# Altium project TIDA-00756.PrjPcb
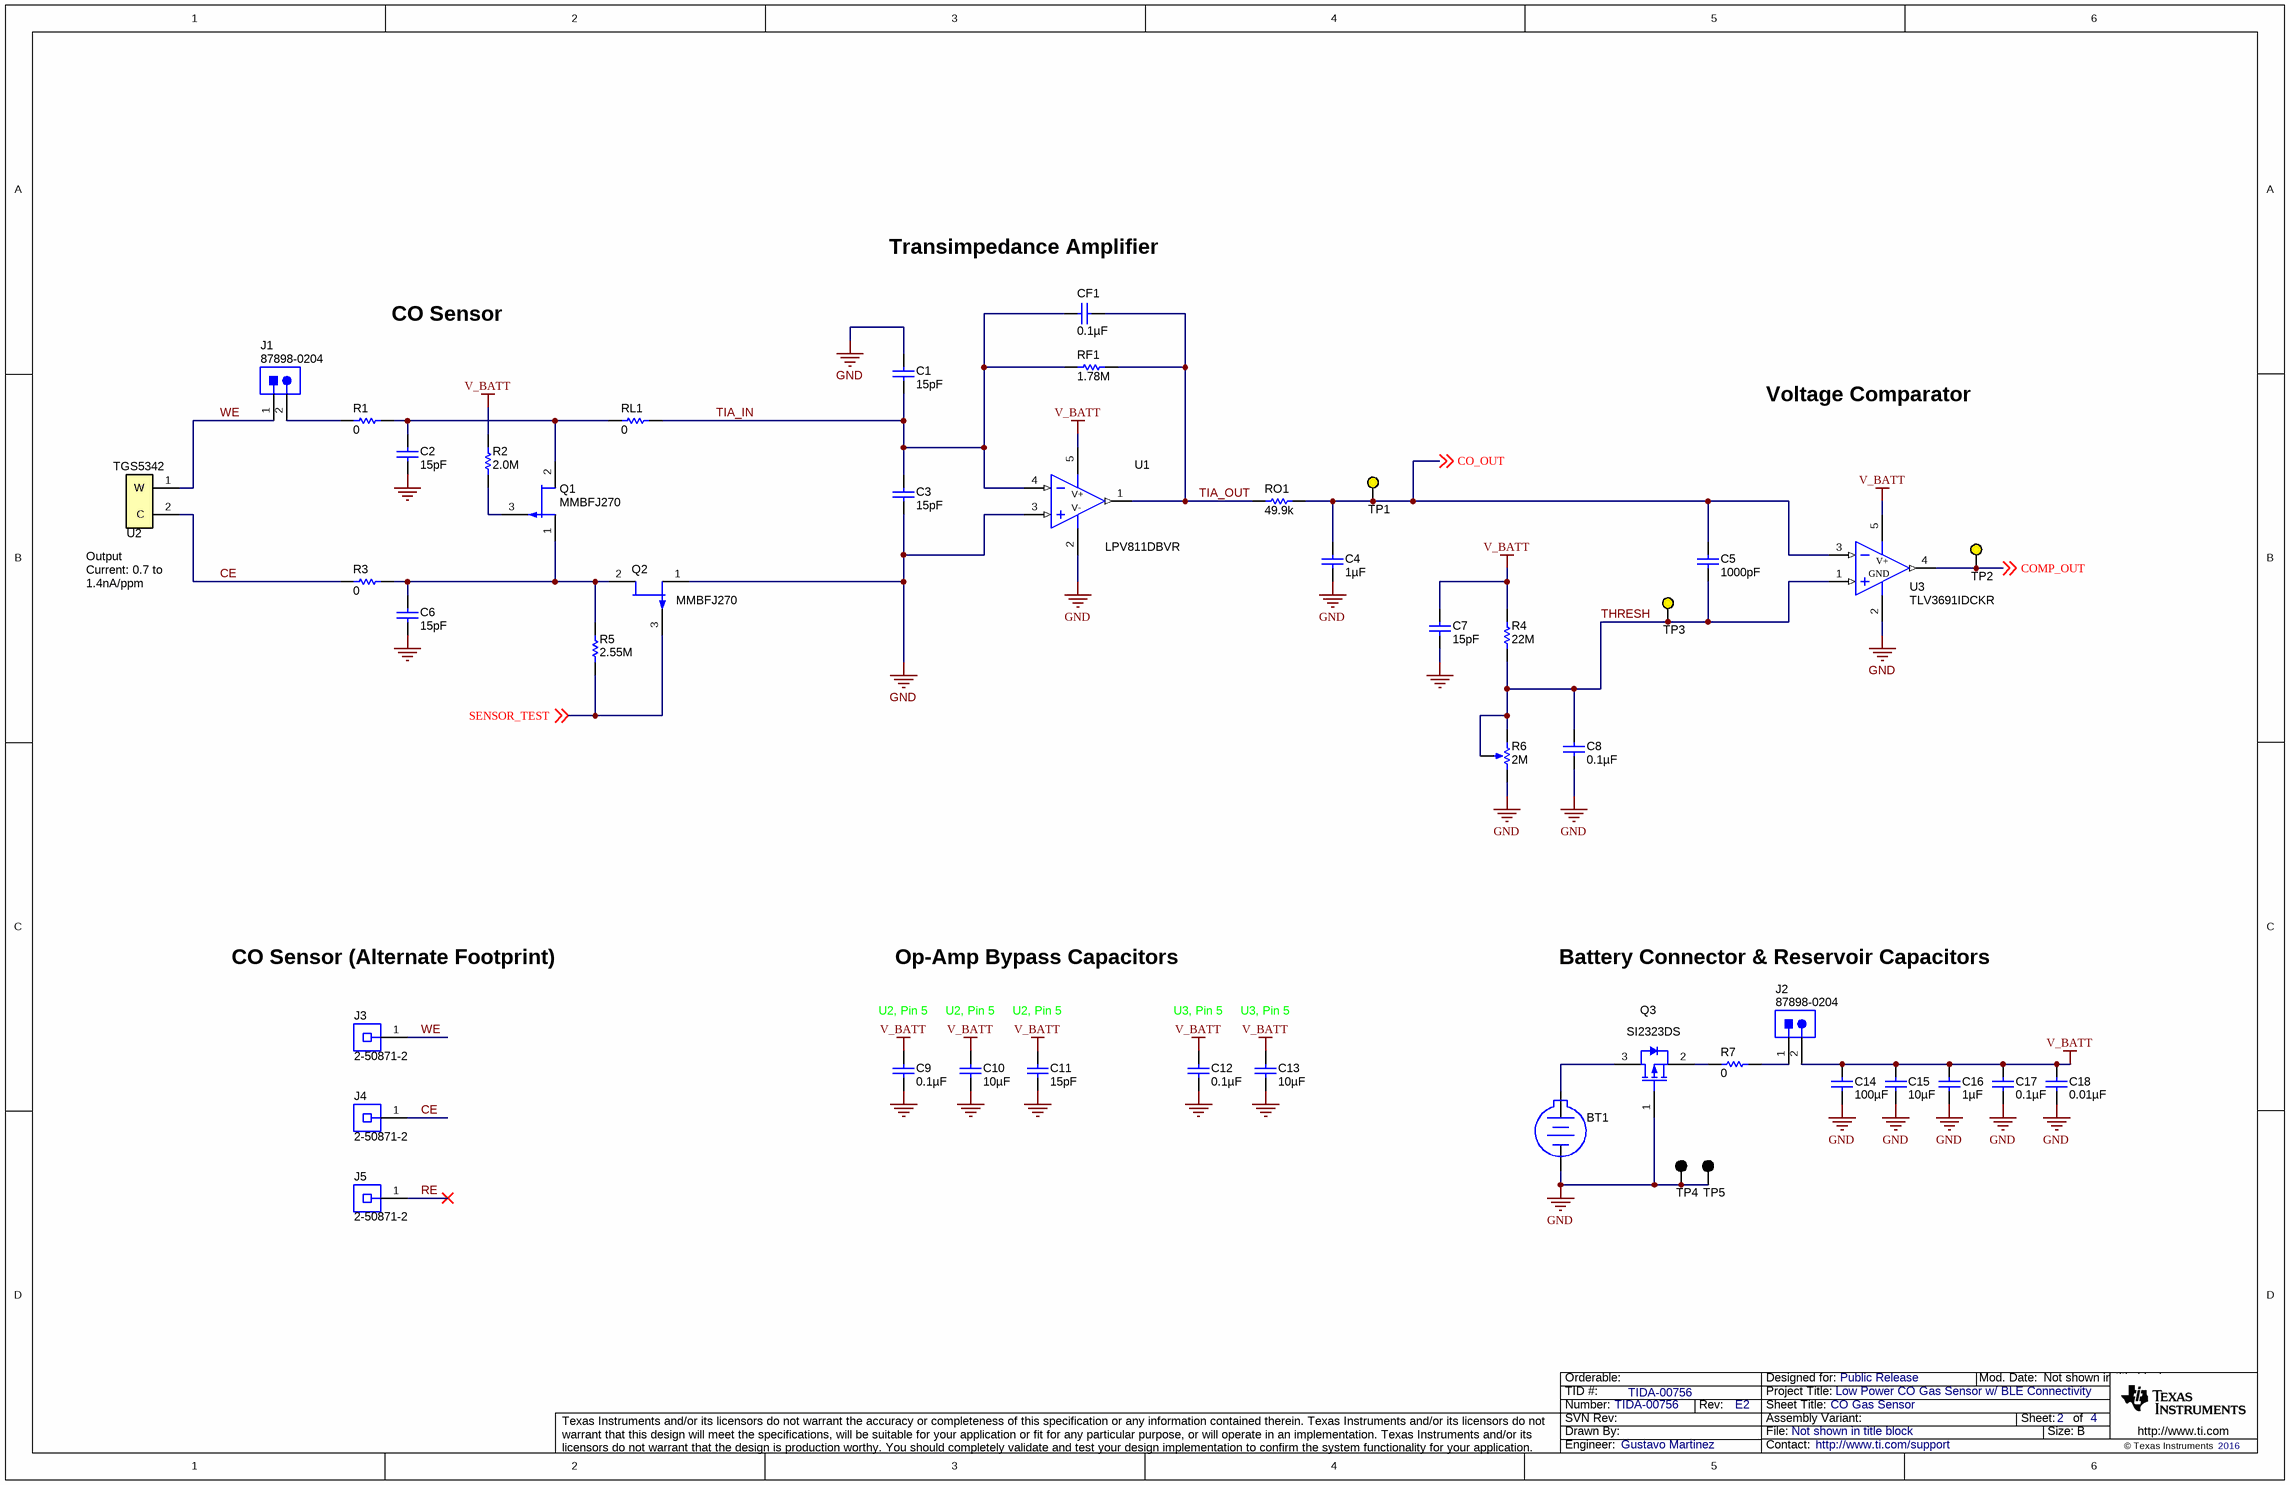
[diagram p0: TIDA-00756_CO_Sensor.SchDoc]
CopyrightYear: 2016; PCB_Layout: Krypton Solutions/RS; PCB_Rev: E2; PRJ_Customer: Public Release; PRJ_Engineer: Gustavo Martinez; PRJ_Number: TIDA-00756; PRJ_Title: Low Power CO Gas Sensor w/ BLE Connectivity; SCH_Rev: E2; TechSupport: http://www.ti.com/support; TID: TIDA-00756
4 sheets, 131 parts. Net scope: global (net labels, ports and power ports of the same name join across sheets).
Board file: TIDA-00756.PcbDoc
Sheets:
  TIDA-00756_CO_Sensor.SchDoc
  TIDA-00756_CoverSheet.SchDoc
  TIDA-00756_Hardware.SchDoc
  TIDA-00756_MCU.SchDoc

## Sheet TIDA-00756_CO_Sensor.SchDoc: CO Gas Sensor
size 431 x 279 mm; Date: Not shown in title block; ApprovedBy: Not shown in title block; CheckedBy: Not shown in title block; Author: Not shown in title block; CompanyName: Not shown in title block; Engineer: Not shown in title block; Organization: Not shown in title block; Address1: Not shown in title block; Address2: Not shown in title block; Address3: Not shown in title block; Address4: Not shown in title block; DocumentNumber: 2; Revision: Use project parameter SCH_Rev; SheetNumber: 2; SheetTotal: 4; PageSetup: Record=PageOptions¦CenterHorizontal=True¦CenterVertical=True¦PrintScale=0.62¦XCorrection=1.00¦YCorrection=1.00¦PrintKind=0¦BorderSize=5000000¦LeftOffset=0¦BottomOffset=0¦Orientation=2¦PaperLength=1000¦PaperWidth=1000¦Scale=100¦PaperSource=15¦PrintQuality=600¦MediaType=1¦DitherType=10¦PrintScaleMode=1¦PaperKind=Letter

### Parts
BT1  BS-7  [BAT_BS-7]  (value not drawn)
C1  ValueDisplayed: 15pF  [0402]  (hidden comment: CC0402JRNPO9BN150)
C2  ValueDisplayed: 15pF  [0402]  (hidden comment: CC0402JRNPO9BN150)
C3  ValueDisplayed: 15pF  [0402]  (hidden comment: CC0402JRNPO9BN150)
C4  ValueDisplayed: 1µF  [0603]  (hidden comment: C1608X5R1E105K080AC)
C5  ValueDisplayed: 1000pF  [0402]  (hidden comment: C0402C102J3RACTU)
C6  ValueDisplayed: 15pF  [0402]  (hidden comment: CC0402JRNPO9BN150)
C7  ValueDisplayed: 15pF  [0402]  (hidden comment: CC0402JRNPO9BN150)
C8  ValueDisplayed: 0.1µF  [0402]  (hidden comment: C1005X7R1H104K)
C9  ValueDisplayed: 0.1µF  [0603L]  (hidden comment: C0603C104K8RACTU)
C10  ValueDisplayed: 10µF  [0805_HV]  (hidden comment: C2012X5R0J106M)
C11  ValueDisplayed: 15pF  [0402]  (hidden comment: CC0402JRNPO9BN150)
C12  ValueDisplayed: 0.1µF  [0603L]  (hidden comment: C0603C104K8RACTU)
C13  ValueDisplayed: 10µF  [0805_HV]  (hidden comment: C2012X5R0J106M)
C14  ValueDisplayed: 100µF  [1206_190]  (hidden comment: C3216X5R1A107M160AC)
C15  ValueDisplayed: 10µF  [0603]  (hidden comment: C1608X5R0J106M)
C16  ValueDisplayed: 1µF  [0603]  (hidden comment: C1608X7R1C105K)
C17  ValueDisplayed: 0.1µF  [0402]  (hidden comment: C1005X7R1H104K050BB)
C18  ValueDisplayed: 0.01µF  [0402]  (hidden comment: C1005X7R1C103K050BA)
CF1  ValueDisplayed: 0.1µF  [0805_HV]  (hidden comment: 08053C104KAT2A)
J1  87898-0204  [Molex_87898-0204]
J2  87898-0204  [Molex_87898-0204]
J3  2-50871-2  [TE_2-50871-2]
J4  2-50871-2  [TE_2-50871-2]
J5  2-50871-2  [TE_2-50871-2]
Q1  MMBFJ270  [SOT-23]
Q2  MMBFJ270  [SOT-23]
Q3  SI2323DS  [SOT-23]
R1  ValueDisplayed: 0  [0603]  (hidden comment: CRCW06030000Z0EA)
R2  ValueDisplayed: 2.0M  [0805_HV]  (hidden comment: CRCW08052M00JNEA)
R3  ValueDisplayed: 0  [0603]  (hidden comment: CRCW06030000Z0EA)
R4  ValueDisplayed: 22M  [0805_HV]  (hidden comment: ERJ-6GEYK226V)
R5  ValueDisplayed: 2.55M  [0805_HV]  (hidden comment: CRCW08052M55FKEA)
R6  value 2M  [TRIM_3224W]  (hidden comment: 3224W-1-205E)
R7  ValueDisplayed: 0  [0805_HV]  (hidden comment: CRCW08050000Z0EA)
RF1  ValueDisplayed: 1.78M  [0805_HV]  (hidden comment: CRCW08051M78FKEA)
RL1  ValueDisplayed: 0  [0805_HV]  (hidden comment: CRCW08050000Z0EA)
RO1  ValueDisplayed: 49.9k  [0603]  (hidden comment: CRCW060349K9FKEA)
TP1  5004  [Keystone5004]  (value not drawn)
TP2  5004  [Keystone5004]  (value not drawn)
TP3  5004  [Keystone5004]  (value not drawn)
TP4  5011  [Keystone5011]  (value not drawn)
TP5  5011  [Keystone5011]  (value not drawn)
U1  LPV811DBVR  [DBV0005A_N]
U2  TGS5342  [FIGARO_TGS5342]
U3  TLV3691IDCKR  [DCK0005A_N]

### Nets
GND: BT1.2(-) C1.1 C2.2 C3.2 C4.2 C6.2 C7.2 C8.2 C9.1 C10.1 C11.2 C12.1 C13.1 C14.2 C15.2 C16.2 C17.2 C18.2 Q2.1(D) Q3.1(G) R6.3(CW) TP4.1 TP5.1 U1.2(V-) U1.3(IN+) U3.2(GND)
V_BATT: C7.1 C9.2 C10.2 C11.1 C12.2 C13.2 C14.1 C15.1 C16.1 C17.1 C18.1 J2.2 R2.1 R4.2 U1.5(V+) U3.5(V+)
CE: J4.1 R3.1 U2.2(C)
CO_OUT: C4.1 C5.1 RO1.2 TP1.1 U3.3(IN-) ; off-sheet CO_OUT
COMP_OUT: TP2.1 U3.4(OUT) ; off-sheet COMP_OUT
RE: J5.1
SENSOR_TEST: Q2.3(G) R5.2 ; off-sheet SENSOR_TEST
THRESH: C5.2 C8.1 R4.1 R6.1(CCW) R6.2(WIPER) TP3.1 U3.1(IN+)
TIA_IN: C1.2 C3.1 CF1.2 RF1.1 RL1.2 U1.4(IN-)
TIA_OUT: CF1.1 RF1.2 RO1.1 U1.1(OUT)
WE: J1.1 J3.1 U2.1(W)
NetBT1_1: BT1.1(+) Q3.3(D)
NetC2_1: C2.1 Q1.2(S) R1.2 RL1.1
NetC6_1: C6.1 Q1.1(D) Q2.2(S) R3.2 R5.1
NetJ1_2: J1.2 R1.1
NetJ2_1: J2.1 R7.2
NetQ1_3: Q1.3(G) R2.2
NetQ3_2: Q3.2(S) R7.1

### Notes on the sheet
- Transimpedance Amplifier
- CO Sensor
- Voltage Comparator
- (near U2) Output Current: 0.7 to 1.4nA/ppm
- CO Sensor (Alternate Footprint)
- Op-Amp Bypass Capacitors
- Battery Connector & Reservoir Capacitors
- U2, Pin 5
- U3, Pin 5

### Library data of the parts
BT1 = BS-7: Battery Holder, CR2032, Retainer clip, TH; Manufacturer: Memory Protection Devices; SymbolCreator: a0412235
C1-C3 C6 C7 C11 = CC0402JRNPO9BN150: CAP, CERM, 15 pF, 50 V, +/- 5%, C0G/NP0, 0402; Manufacturer: Yageo America; Polarized: N; CompType: Capacitor; Value: 15pF; U/M: EA; Cap_F: 0.000000000015; Tolerance_%: 5; Value1: Unknown; VDC_V: 50; Value2: 50V; TaMin_C: -55; TaMax_C: 125; AEC Category: Q200
C4 = C1608X5R1E105K080AC: CAP, CERM, 1 µF, 25 V, +/- 10%, X5R, 0603; Manufacturer: TDK; Polarized: N; CompType: Capacitor; Value: 1uF; U/M: EA; Cap_F: 0.000001; Tolerance_%: 10; Value1: Unknown; VDC_V: 25; Value2: 25V; TaMin_C: -55; TaMax_C: 85; AEC Category: Q200
C5 = C0402C102J3RACTU: CAP, CERM, 1000 pF, 25 V, +/- 5%, X7R, 0402; Manufacturer: Kemet; Polarized: N; CompType: Capacitor; Value: 1000pF; U/M: EA; Cap_F: 0.000000001; Tolerance_%: 5; Value1: Unknown; VDC_V: 25; Value2: 25V; TaMin_C: -55; TaMax_C: 125; AEC Category: Q200
C8 = C1005X7R1H104K: CAP, CERM, 0.1 µF, 50 V, +/- 10%, X7R, 0402; Manufacturer: TDK; Polarized: N; CompType: Capacitor; Value: 0.1uF; U/M: EA; Cap_F: 0.0000001; Tolerance_%: 10; Value1: Unknown; VDC_V: 50; Value2: 50V; TaMin_C: -55; TaMax_C: 125; AEC Category: Q200
C9 C12 = C0603C104K8RACTU: CAP, CERM, 0.1 µF, 10 V, +/- 10%, X7R, 0603; Manufacturer: Kemet; Polarized: N; CompType: Capacitor; Value: 0.1uF; U/M: EA; Cap_F: 0.0000001; Tolerance_%: 10; Value1: Unknown; Value2: 10V; TaMin_C: -55; TaMax_C: 125; Cap_Case: 0603
C10 C13 = C2012X5R0J106M: CAP, CERM, 10 µF, 6.3 V, +/- 20%, X5R, 0805; Manufacturer: TDK; Polarized: N; CompType: Capacitor; Value: 10uF; U/M: EA; Cap_F: 0.00001; Tolerance_%: 20; ESR_ohm: 0.0026; Value1: 0.0026 ohm; VDC_V: 6.3; Value2: 6.3V; TaMin_C: -55; TaMax_C: 85; Cap_Case: 0805
C14 = C3216X5R1A107M160AC: CAP, CERM, 100 µF, 10 V, +/- 20%, X5R, 1206_190; Manufacturer: TDK; Polarized: N; CompType: Capacitor; Value: 100uF; U/M: EA; Cap_F: 0.0001; Tolerance_%: 20; Value1: Unknown; VDC_V: 10; Value2: 10V; TaMin_C: -55; TaMax_C: 85; Cap_Case: 1206; AEC Category: Q200
C15 = C1608X5R0J106M: CAP, CERM, 10 µF, 6.3 V, +/- 20%, X5R, 0603; Manufacturer: TDK; Polarized: N; CompType: Capacitor; Value: 10uF; U/M: EA; Cap_F: 0.00001; Tolerance_%: 20; ESR_ohm: 0.005; Value1: 0.005 ohm; VDC_V: 6.3; Value2: 6.3V; IRMS_A: 1.9; TaMin_C: -25; TaMax_C: 85; AEC Category: Q200
C16 = C1608X7R1C105K: CAP, CERM, 1 µF, 16 V, +/- 10%, X7R, 0603; Manufacturer: TDK; Polarized: N; CompType: Capacitor; Value: 1uF; U/M: EA; Cap_F: 0.000001; Tolerance_%: 10; ESR_ohm: 0.0057; Value1: 0.0057 ohm; VDC_V: 16; Value2: 16V; TaMin_C: -55; TaMax_C: 125; AEC Category: Q200
C17 = C1005X7R1H104K050BB: CAP, CERM, 0.1 µF, 50 V, +/- 10%, X7R, 0402; Manufacturer: TDK; Polarized: N; CompType: Capacitor; Value: 0.1uF; U/M: EA; Cap_F: 0.0000001; Tolerance_%: 10; Value1: Unknown; VDC_V: 50; Value2: 50V; TaMin_C: -55; TaMax_C: 125; AEC Category: Q200
C18 = C1005X7R1C103K050BA: CAP, CERM, 0.01 µF, 16 V, +/- 10%, X7R, 0402; Manufacturer: TDK; Polarized: N; CompType: Capacitor; Value: 0.01uF; U/M: EA; Cap_F: 0.00000001; Tolerance_%: 10; ESR_ohm: 0.0623; Value1: 0.0623 ohm; VDC_V: 16; Value2: 16V; TaMin_C: -55; TaMax_C: 125; AEC Category: Q200
CF1 = 08053C104KAT2A: CAP, CERM, 0.1 µF, 25 V, +/- 10%, X7R, 0805; Manufacturer: AVX; Polarized: N; CompType: Capacitor; Value: 0.1uF; U/M: EA; Cap_F: 0.0000001; Tolerance_%: 10; ESR_ohm: 0.28; Value1: 0.28 ohm; VDC_V: 25; Value2: 25V; TaMin_C: -55; TaMax_C: 125; Cap_Case: 0805; AEC Category: Q200
J1 J2 = 87898-0204: Header, 2.54 mm, 2x1, Gold, R/A, SMT; Manufacturer: Molex; SymbolCreator: a0412235; U/M: EA
J3-J5 = 2-50871-2: CONN SOCKET RCPT .056-.065 30AU, Gold, TH; Manufacturer: TE Connectivity; SymbolCreator: a0799628; CompType: Pin Receptacle
Q1 Q2 = MMBFJ270: JFET, P-CH, -30 V, -0.015 A, SOT-23; Manufacturer: Fairchild Semiconductor; Alternate Manufacturer: None; SymbolCreator: Altium; CompType: MOSFET; U/M: EA; ChType: P; Value: -30V; Value1: ? ohm; Value2: ? nC; Vgs_V: 30; AEC Category: Q101; AEC Qualified: N
Q3 = SI2323DS: MOSFET, P-CH, -20 V, -3.7 A, SOT-23; Manufacturer: Vishay-Siliconix; Alternate Manufacturer: None; U/M: EA; ChType: P; Value: -20V; Value1: 0.031 ohm; Rdson45_ohm: 0.031; Value2: 12.5 nC; QgTyp_nC: 12.5; Vgs_V: -8; AEC Category: Q101
R1 R3 = CRCW06030000Z0EA: RES, 0, 5%, 0.1 W, 0603; Manufacturer: Vishay-Dale; CompType: Resistor; Value: 0; Value_Code: 0000; Tolerance_%: 5; Power_W: 0.1; Value2: 0.1W; VDC_V: 75; TempCo: 200 ppm/C; EIA_Code: E24; U/M: EA; AEC Category: Q200
R2 = CRCW08052M00JNEA: RES, 2.0 M, 5%, 0.125 W, 0805; Manufacturer: Vishay-Dale; CompType: Resistor; Value: 2.0Meg; Res_ohm: 2000000; Value_Code: 2M00; Tolerance_%: 5; Power_W: 0.125; Value2: 0.125W; VDC_V: 150; TempCo: 200 ppm/C; EIA_Code: E24; U/M: EA; AEC Category: Q200
R4 = ERJ-6GEYK226V: RES, 22 M, 10%, 0.125 W, 0805; Manufacturer: Panasonic; CompType: Resistor; Value: 22Meg; Res_ohm: 22000000; Value_Code: 22M0; Tolerance_%: 10; Power_W: 0.125; Value2: 0.125W; VDC_V: 150; TempCo: 150 ppm/C; U/M: EA; AEC Category: Q200
R5 = CRCW08052M55FKEA: RES, 2.55 M, 1%, 0.125 W, 0805; Manufacturer: Vishay-Dale; CompType: Resistor; Value: 2.55Meg; Res_ohm: 2550000; Value_Code: 2M55; Tolerance_%: 1; Power_W: 0.125; Value2: 0.125W; VDC_V: 150; TempCo: 100 ppm/C; EIA_Code: E96; U/M: EA; AEC Category: Q200
R6 = 3224W-1-205E: TRIMMER 2M OHM 0.25W SMD; Manufacturer: Bourns; Sim Note: Enter the Resistance value and the set point into parameter fields.; SymbolCreator: a0412235
R7 RL1 = CRCW08050000Z0EA: RES, 0, 5%, 0.125 W, 0805; Manufacturer: Vishay-Dale; CompType: Resistor; Value: 0; Value_Code: 0000; Tolerance_%: 5; Power_W: 0.125; Value2: 0.125W; VDC_V: 150; TempCo: 200 ppm/C; EIA_Code: E24; U/M: EA; AEC Category: Q200
RF1 = CRCW08051M78FKEA: RES, 1.78 M, 1%, 0.125 W, 0805; Manufacturer: Vishay-Dale; CompType: Resistor; Value: 1.78Meg; Res_ohm: 1780000; Value_Code: 1M78; Tolerance_%: 1; Power_W: 0.125; Value2: 0.125W; VDC_V: 150; TempCo: 100 ppm/C; EIA_Code: E96; U/M: EA; AEC Category: Q200
RO1 = CRCW060349K9FKEA: RES, 49.9 k, 1%, 0.1 W, 0603; Manufacturer: Vishay-Dale; CompType: Resistor; Value: 49.9k; Res_ohm: 49900; Value_Code: 49k9; Tolerance_%: 1; Power_W: 0.1; Value2: 0.1W; VDC_V: 75; TempCo: 100 ppm/C; EIA_Code: E96; U/M: EA; AEC Category: Q200
TP1-TP3 = 5004: Test Point, Miniature, Yellow, TH; Manufacturer: Keystone; CompType: Test Point Loop; U/M: EA
TP4 TP5 = 5011: Test Point, Multipurpose, Black, TH; Manufacturer: Keystone; CompType: Test Point Loop; ContactFinish: Silver
U1 = LPV811DBVR: Precision 425 nA Nanopower Operational Amplifier, DBV0005A (SOT-5); Alternate PartNumber: LPV811DBVT; Manufacturer: Texas Instruments; SizeArea_mm2: 8.12; SizeAreaWB_mm2: 14.82; SizeX_mm: 2.8; SizeY_mm: 2.9; SizeZ_mm: 1.45; CompType: IC; U/M: EA
U2 = TGS5342: Carbon Monoxide Detector, TH; Manufacturer: Any; SymbolCreator: Altium
U3 = TLV3691IDCKR: 0.9-V to 6.5-V, Nanopower Comparator, DCK0005A; Alternate PartNumber: TLV3691IDCKT; Manufacturer: Texas Instruments; SymbolCreator: OpAmp IC; CompType: IC; U/M: EA

## Sheet TIDA-00756_CoverSheet.SchDoc: Cover Sheet
size 431 x 279 mm; Date: Not shown in title block; ApprovedBy: Not shown in title block; CheckedBy: Not shown in title block; Author: Not shown in title block; CompanyName: Not shown in title block; Engineer: Not shown in title block; Organization: Not shown in title block; Address1: Not shown in title block; Address2: Not shown in title block; Address3: Not shown in title block; Address4: Not shown in title block; DocumentNumber: 1; Revision: Use project parameter SCH_Rev; SheetNumber: 1; SheetTotal: 4; PageSetup: Record=PageOptions¦CenterHorizontal=True¦CenterVertical=True¦PrintScale=1.00¦XCorrection=1.00¦YCorrection=1.00¦PrintKind=0¦BorderSize=5000000¦LeftOffset=0¦BottomOffset=0¦Orientation=2¦PaperLength=1000¦PaperWidth=1000¦Scale=100¦PaperSource=15¦PrintQuality=600¦MediaType=1¦DitherType=10¦PaperKind=Letter¦PrintScaleMode=1
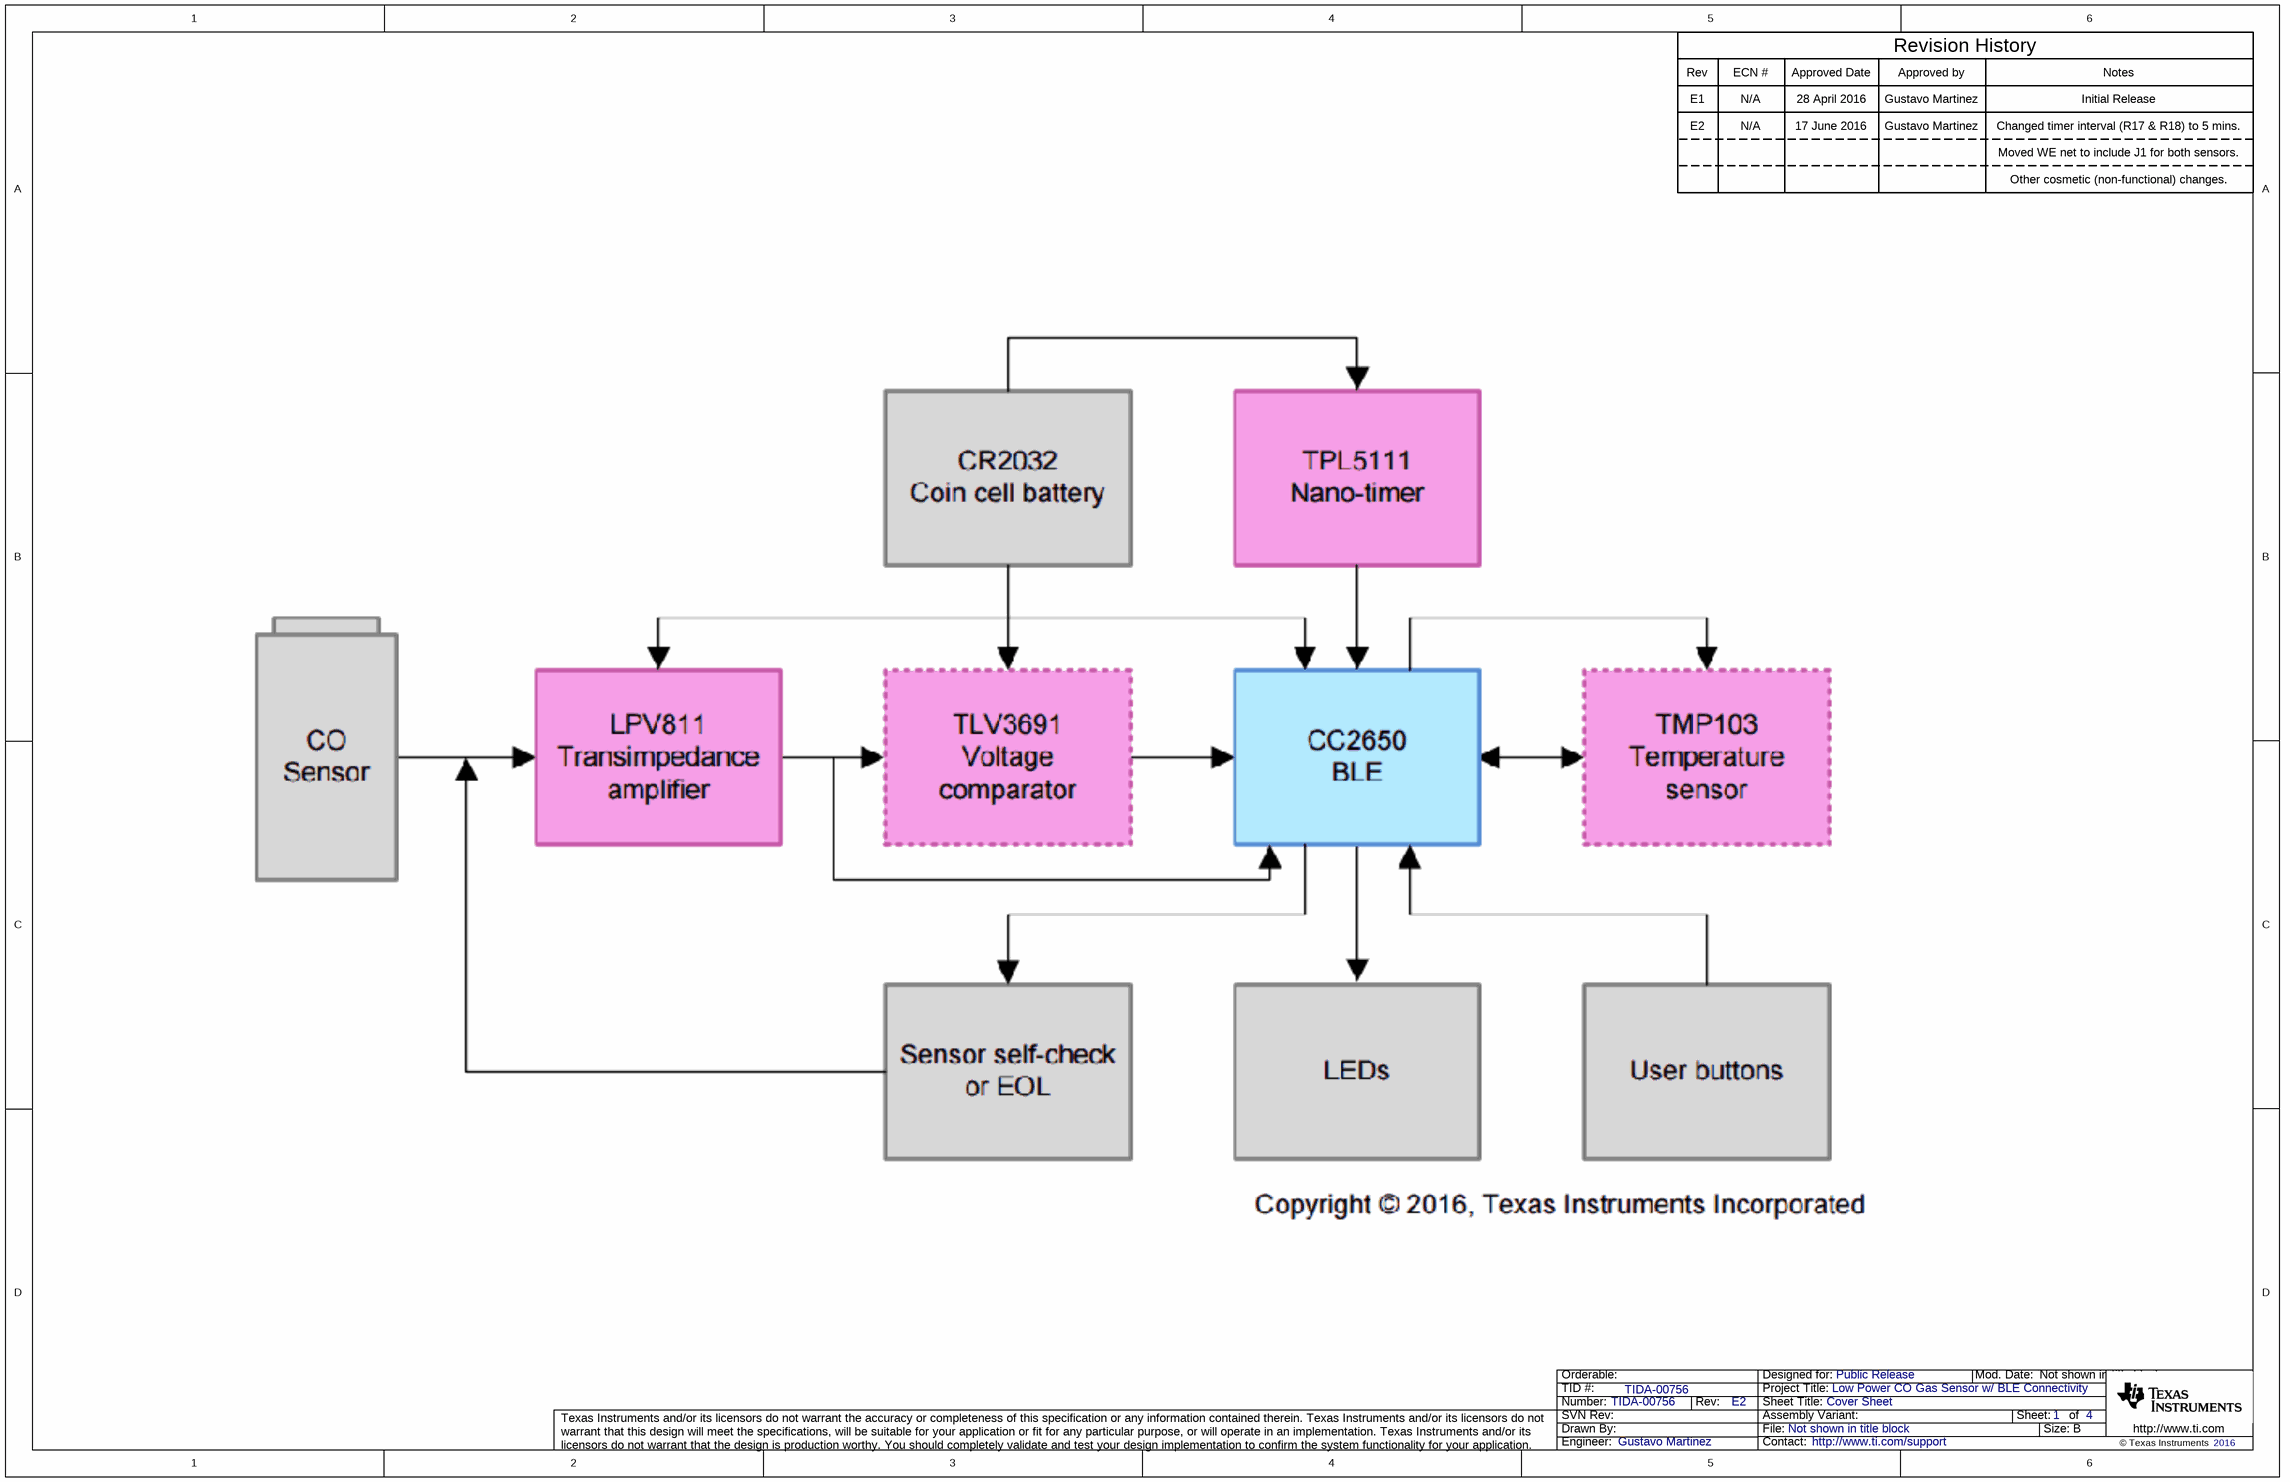
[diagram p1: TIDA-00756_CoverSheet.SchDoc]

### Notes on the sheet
- Rev
- E1
- ECN #
- N/A
- Approved Date
- 28 April 2016
- Approved by
- Gustavo Martinez
- Revision History
- Notes
- Initial Release
- E2
- 17 June 2016
- Changed timer interval (R17 & R18) to 5 mins.
- Moved WE net to include J1 for both sensors.
- Other cosmetic (non-functional) changes.

## Sheet TIDA-00756_Hardware.SchDoc: Hardware
size 431 x 279 mm; Date: Not shown in title block; ApprovedBy: Not shown in title block; CheckedBy: Not shown in title block; Author: Not shown in title block; CompanyName: Not shown in title block; Engineer: Not shown in title block; Organization: Not shown in title block; Address1: Not shown in title block; Address2: Not shown in title block; Address3: Not shown in title block; Address4: Not shown in title block; DocumentNumber: 4; Revision: Use project parameter SCH_Rev; SheetNumber: 4; SheetTotal: 4; PageSetup: Record=PageOptions¦CenterHorizontal=True¦CenterVertical=True¦PrintScale=1.00¦XCorrection=1.00¦YCorrection=1.00¦PrintKind=0¦BorderSize=5000000¦LeftOffset=0¦BottomOffset=0¦Orientation=2¦PaperLength=1000¦PaperWidth=1000¦Scale=100¦PaperSource=15¦PrintQuality=600¦MediaType=1¦DitherType=10¦PaperKind=Letter¦PrintScaleMode=1
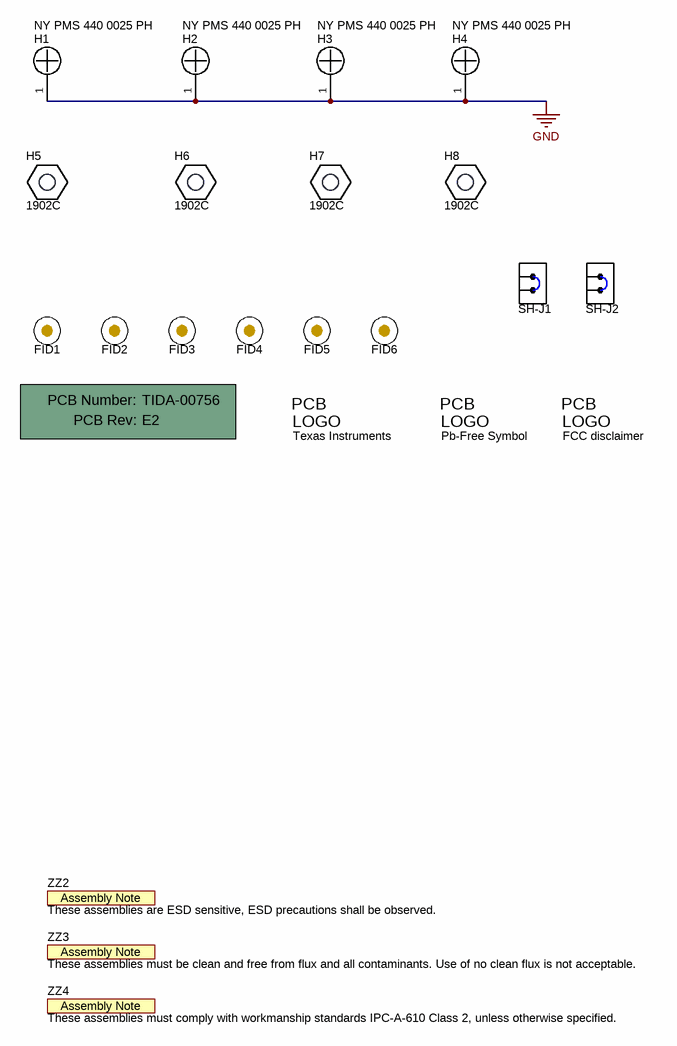
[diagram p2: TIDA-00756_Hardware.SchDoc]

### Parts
!PCB1  Printed Circuit Board  (value not drawn)  (mechanical)
FID1  Fiducial  [Fiducial10-20]  (value not drawn)
FID2  Fiducial  [Fiducial10-20]  (value not drawn)
FID3  Fiducial  [Fiducial10-20]  (value not drawn)
FID4  Fiducial  [Fiducial10-20]  (value not drawn)
FID5  Fiducial  [Fiducial10-20]  (value not drawn)
FID6  Fiducial  [Fiducial10-20]  (value not drawn)
H1  NY PMS 440 0025 PH  [NY PMS 440 0025 PH]
H2  NY PMS 440 0025 PH  [NY PMS 440 0025 PH]
H3  NY PMS 440 0025 PH  [NY PMS 440 0025 PH]
H4  NY PMS 440 0025 PH  [NY PMS 440 0025 PH]
H5  1902C  [Keystone_1902C]
H6  1902C  [Keystone_1902C]
H7  1902C  [Keystone_1902C]
H8  1902C  [Keystone_1902C]
Logo1  Texas Instruments  [TI_Stacked_Overlay_Small]  (no BOM)
Logo2  Pb-Free Symbol  [Pb-Free_Overlay_Small]  (no BOM)
Logo3  FCC disclaimer  [FCC_disclaimer_stacked]  (no BOM)
SH-J1  969102-0000-DA  [SNT-100-BK-G]  (value not drawn)
SH-J2  969102-0000-DA  [SNT-100-BK-G]  (value not drawn)
ZZ2  These assemblies are ESD sensitive, ESD precautions shall be observed.  [AssemblyNote]  (no BOM)
ZZ3  These assemblies must be clean and free from flux and all contaminants. Use of no clean flux is not acceptable.  [AssemblyNote]  (no BOM)
ZZ4  These assemblies must comply with workmanship standards IPC-A-610 Class 2, unless otherwise specified.  [AssemblyNote]  (no BOM)

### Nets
GND: H1.1 H2.1 H3.1 H4.1

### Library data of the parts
!PCB1 = PCB: Manufacturer: Any; PartNumber: TIDA-00756; SymbolCreator: a0412235
FID1-FID6 = Fiducial: Fiducial mark.  There is nothing to buy or mount.; SymbolCreator: codlsc
H1-H4 = NY PMS 440 0025 PH: Machine Screw, Round, #4-40 x 1/4, Nylon, Philips panhead; Manufacturer: B&F Fastener Supply; CompType: Hardware; SymbolCreator: codlsc; U/M: EA
H5-H8 = 1902C: Standoff, Hex, 0.5"L #4-40 Nylon; Manufacturer: Keystone; CompType: Hardware
Logo1 = TI_Logo: Texas Instrument Corporate Signature; SymbolCreator: codlsc
Logo2 = Pb-Free: SymbolCreator: a0412235
Logo3 = FCC_disclaimer: SymbolCreator: codlsc
SH-J1 SH-J2 = 969102-0000-DA: Shunt, 100mil, Gold plated, Black; Manufacturer: 3M; Alternate Manufacturer: Samtec; Value: 1x2; Note: You can "mate" this to a header by matching the designator.  i.e. use SH-J3 for header J3
ZZ2-ZZ4 = AssemblyNote: SymbolCreator: codlsc

## Sheet TIDA-00756_MCU.SchDoc: Wireless MCU
size 431 x 279 mm; Date: Not shown in title block; ApprovedBy: Not shown in title block; CheckedBy: Not shown in title block; Author: Not shown in title block; CompanyName: Not shown in title block; Engineer: Not shown in title block; Organization: Not shown in title block; Address1: Not shown in title block; Address2: Not shown in title block; Address3: Not shown in title block; Address4: Not shown in title block; DocumentNumber: 3; Revision: Use project parameter SCH_Rev; SheetNumber: 3; SheetTotal: 4; PageSetup: Record=PageOptions¦CenterHorizontal=True¦CenterVertical=True¦PrintScale=1.00¦XCorrection=1.00¦YCorrection=1.00¦PrintKind=0¦BorderSize=5000000¦LeftOffset=0¦BottomOffset=0¦Orientation=2¦PaperLength=1000¦PaperWidth=1000¦Scale=100¦PaperSource=15¦PrintQuality=600¦MediaType=1¦DitherType=10¦PaperKind=Letter¦PrintScaleMode=1
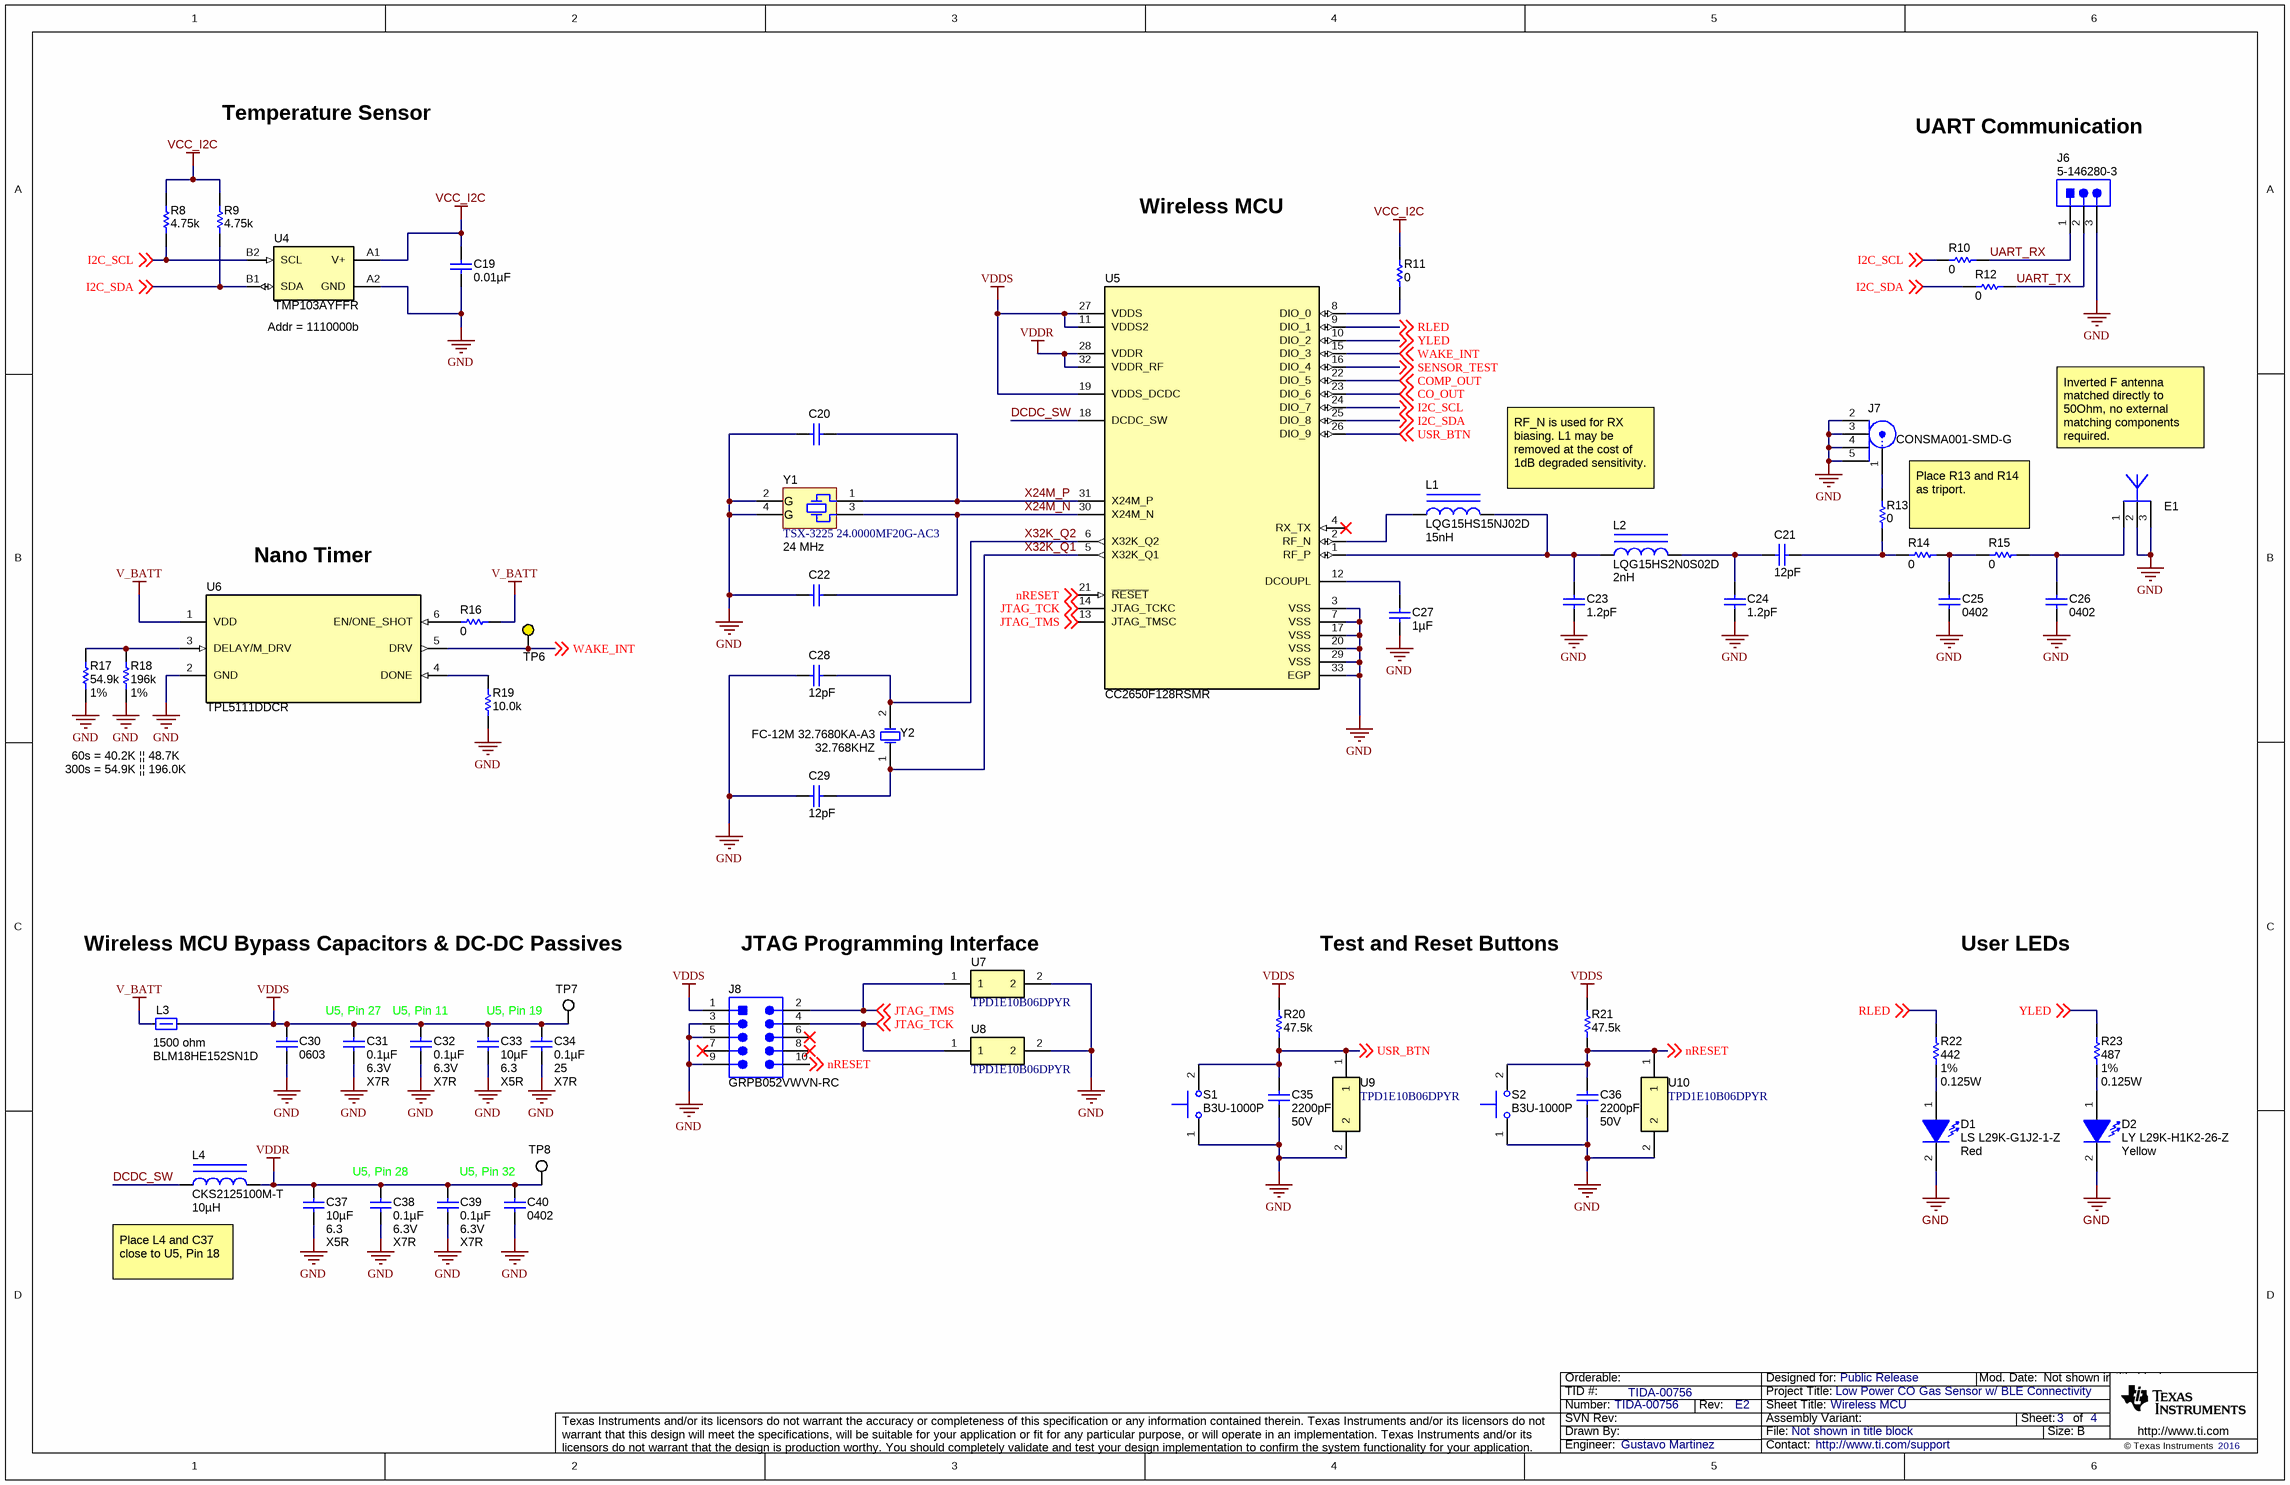
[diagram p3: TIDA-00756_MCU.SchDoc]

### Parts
C19  ValueDisplayed: 0.01µF  [0402]  (hidden comment: GRM155R71C103KA01D)
C20  GRM1555C1E120JA01D  [0402]  (value not drawn)
C21  ValueDisplayed: 12pF  [0402S]  (hidden comment: GRM1555C1H120JA01D)
C22  GRM1555C1E120JA01D  [0402]  (value not drawn)
C23  ValueDisplayed: 1.2pF  [0402S]  (hidden comment: GRM1555C1H1R2BA01D)
C24  ValueDisplayed: 1.2pF  [0402S]  (hidden comment: GRM1555C1H1R2BA01D)
C25  PackageReference: 0402  [0402S]  (hidden comment: Used in BOM report)
C26  PackageReference: 0402  [0402S]  (hidden comment: Used in BOM report)
C27  ValueDisplayed: 1µF  [0402]  (hidden comment: GRM155R61A105KE15D)
C28  ValueDisplayed: 12pF  [0402]  (hidden comment: GRM1555C1E120JA01D)
C29  ValueDisplayed: 12pF  [0402]  (hidden comment: GRM1555C1E120JA01D)
C30  Used in BOM report  [0603]  (value not drawn)
C31  ValueDisplayed: 0.1µF  Value2: 6.3V  TempCo: X7R  [0402S]  (hidden comment: GRM155R70J104KA01D)
C32  ValueDisplayed: 0.1µF  Value2: 6.3V  TempCo: X7R  [0402]  (hidden comment: GRM155R70J104KA01D)
C33  ValueDisplayed: 10µF  VDC_V: 6.3  TempCo: X5R  [0603]  (hidden comment: GRM188R60J106ME47D)
C34  ValueDisplayed: 0.1µF  VDC_V: 25  TempCo: X7R  [0603]  (hidden comment: GRM188R71E104KA01D)
C35  ValueDisplayed: 2200pF  Value2: 50V  [0402]  (hidden comment: C1005X7R1H222K)
C36  ValueDisplayed: 2200pF  Value2: 50V  [0402]  (hidden comment: C1005X7R1H222K)
C37  ValueDisplayed: 10µF  VDC_V: 6.3  TempCo: X5R  [0603]  (hidden comment: GRM188R60J106ME47D)
C38  ValueDisplayed: 0.1µF  Value2: 6.3V  TempCo: X7R  [0402S]  (hidden comment: GRM155R70J104KA01D)
C39  ValueDisplayed: 0.1µF  Value2: 6.3V  TempCo: X7R  [0402S]  (hidden comment: GRM155R70J104KA01D)
C40  PackageReference: 0402  [0402S]  (hidden comment: Used in BOM report)
D1  LS L29K-G1J2-1-Z  value Red  [LS L29K_Red]
D2  LY L29K-H1K2-26-Z  value Yellow  [LY L29K_Yellow]
E1  ANTENNA_DN007A  [ANTENNA_DN007A]  (value not drawn)  (net tie)
J6  5-146280-3  [TE_5-146280-3]
J7  CONSMA001-SMD-G  [Linx_CONSMA001-SMD-G]
J8  GRPB052VWVN-RC  [CONN_GRPB052VWVN-RC]
L1  LQG15HS15NJ02D  ValueDisplayed: 15nH  [IND_LQG15H]
L2  LQG15HS2N0S02D  ValueDisplayed: 2nH  [IND_LQG15H]
L3  value 1500 ohm  [0603]  (hidden comment: BLM18HE152SN1D)
L4  CKS2125100M-T  ValueDisplayed: 10µH  [0805_145]
R8  ValueDisplayed: 4.75k  [0402]  (hidden comment: CRCW04024K75FKED)
R9  ValueDisplayed: 4.75k  [0402]  (hidden comment: CRCW04024K75FKED)
R10  ValueDisplayed: 0  [0805_HV]  (hidden comment: CRCW08050000Z0EA)
R11  ValueDisplayed: 0  [0402]  (hidden comment: CRCW04020000Z0ED)
R12  ValueDisplayed: 0  [0805_HV]  (hidden comment: CRCW08050000Z0EA)
R13  ValueDisplayed: 0  [0402S]  (hidden comment: CRCW04020000Z0ED)
R14  ValueDisplayed: 0  [0402S]  (hidden comment: CRCW04020000Z0ED)
R15  ValueDisplayed: 0  [0402S]  (hidden comment: CRCW04020000Z0ED)
R16  ValueDisplayed: 0  [0402]  (hidden comment: CRCW04020000Z0ED)
R17  ValueDisplayed: 54.9k  Value1: 1%  [0805_HV]  (hidden comment: ERJ-6ENF5492V)
R18  ValueDisplayed: 196k  Value1: 1%  [0805_HV]  (hidden comment: ERJ-6ENF1963V)
R19  ValueDisplayed: 10.0k  [0402]  (hidden comment: CRCW040210K0FKED)
R20  ValueDisplayed: 47.5k  [0402]  (hidden comment: CRCW040247K5FKED)
R21  ValueDisplayed: 47.5k  [0402]  (hidden comment: CRCW040247K5FKED)
R22  ValueDisplayed: 442  Value1: 1%  Value2: 0.125W  [0805_HV]  (hidden comment: CRCW0805442RFKEA)
R23  ValueDisplayed: 487  Value1: 1%  Value2: 0.125W  [0805_HV]  (hidden comment: CRCW0805487RFKEA)
S1  B3U-1000P  [SW_B3U-1000P]
S2  B3U-1000P  [SW_B3U-1000P]
TP6  5004  [Keystone5004]  (value not drawn)
TP7  5015  [Testpoint_Keystone_Miniature]  (value not drawn)
TP8  5015  [Testpoint_Keystone_Miniature]  (value not drawn)
U4  TMP103AYFFR  [YFF0004AAAA]
U5  CC2650F128RSMR  [RSM0032B]
U6  TPL5111DDCR  [DDC0006A_N]
U7  TPD1E10B06DPYR  [DPY0002A]
U8  TPD1E10B06DPYR  [DPY0002A]
U9  TPD1E10B06DPYR  [DPY0002A]
U10  TPD1E10B06DPYR  [DPY0002A]
Y1  TSX-3225 24.0000MF20G-AC3  Frequency: 24 MHz  [EPSON_TSX-3225]
Y2  FC-12M 32.7680KA-A3  Frequency: 32.768KHZ  [Epson_FC-12M]

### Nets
GND: C19.2 C20.1 C22.1 C23.2 C24.2 C25.1 C26.1 C27.2 C28.2 C29.2 C30.2 C31.2 C32.2 C33.1 C34.1 C35.1 C36.1 C37.1 C38.2 C39.2 C40.2 D1.2(K) D2.2(K) E1.2 E1.3 J6.3 J7.2 J7.3 J7.4 J7.5 J8.3 J8.5 J8.9 R17.1 R18.2 R19.1 S1.1 S2.1 U4.A2(GND) U5.3(VSS) U5.7(VSS) U5.17(VSS) U5.20(VSS) U5.29(VSS) U5.33(EGP) U6.2(GND) U7.2 U8.2 U9.2 U10.2 Y1.2(GND) Y1.4(GND)
V_BATT: L3.1 R16.2 U6.1(VDD)
VCC_I2C: C19.1 R8.2 R9.2 R11.2 U4.A1(V+)
VDDR: C37.2 C38.1 C39.1 C40.1 L4.2 TP8.1 U5.28(VDDR) U5.32(VDDR_RF)
VDDS: C30.1 C31.1 C32.1 C33.2 C34.2 J8.1 L3.2 R20.2 R21.2 TP7.1 U5.11(VDDS2) U5.19(VDDS_DCDC) U5.27(VDDS)
CO_OUT: U5.23(DIO_6) ; off-sheet CO_OUT
COMP_OUT: U5.22(DIO_5) ; off-sheet COMP_OUT
DCDC_SW: L4.1 U5.18(DCDC_SW)
I2C_SCL: R8.1 R10.2 U4.B2(SCL) U5.24(DIO_7) ; off-sheet I2C_SCL
I2C_SDA: R9.1 R12.2 U4.B1(SDA) U5.25(DIO_8) ; off-sheet I2C_SDA
JTAG_TCK: J8.4 U5.14(JTAG_TCKC) U8.1 ; off-sheet JTAG_TCK
JTAG_TMS: J8.2 U5.13(JTAG_TMSC) U7.1 ; off-sheet JTAG_TMS
nRESET: C36.2 J8.10 R21.1 S2.2 U5.21(~{RESET}) U10.1 ; off-sheet nRESET
RLED: R22.1 U5.9(DIO_1) ; off-sheet RLED
SENSOR_TEST: U5.16(DIO_4) ; off-sheet SENSOR_TEST
UART_RX: J6.1 R10.1
UART_TX: J6.2 R12.1
USR_BTN: C35.2 R20.1 S1.2 U5.26(DIO_9) U9.1 ; off-sheet USR_BTN
WAKE_INT: TP6.1 U5.15(DIO_3) U6.5(DRV) ; off-sheet WAKE_INT
X24M_N: C22.2 U5.30(X24M_N) Y1.3
X24M_P: C20.2 U5.31(X24M_P) Y1.1
X32K_Q1: C29.1 U5.5(X32K_Q1) Y2.1(OSC1)
X32K_Q2: C28.1 U5.6(X32K_Q2) Y2.2(OSC2)
YLED: R23.1 U5.10(DIO_2) ; off-sheet YLED
NetC21_1: C21.1 R13.1 R14.1
NetC21_2: C21.2 C24.1 L2.2
NetC23_1: C23.1 L1.2 L2.1 U5.1(RF_P)
NetC25_2: C25.2 R14.2 R15.1
NetC26_2: C26.2 E1.1 R15.2
NetC27_1: C27.1 U5.12(DCOUPL)
NetD1_1: D1.1(A) R22.2
NetD2_1: D2.1(A) R23.2
NetJ7_1: J7.1 R13.2
NetL1_1: L1.1 U5.2(RF_N)
NetR11_1: R11.1 U5.8(DIO_0)
NetR16_1: R16.1 U6.6(EN/ONE_SHOT)
NetR17_2: R17.2 R18.1 U6.3(DELAY/M_DRV)
NetR19_2: R19.2 U6.4(DONE)

Not connected (* = marked no-connect by the designer): J8 6* 7* 8*; U5 4(RX_TX)*

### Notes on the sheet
- Temperature Sensor
- UART Communication
- Wireless MCU
- (near U4) Addr = 1110000b
- (near L1) RF_N is used for RX biasing. L1 may be removed at the cost of 1dB degraded sensitivity.
- Inverted F antenna matched directly to 50Ohm, no external matching components required.
- Nano Timer
- Place R13 and R14 as triport.
- 60s = 40.2K ¦¦ 48.7K
- 300s = 54.9K ¦¦ 196.0K
- Wireless MCU Bypass Capacitors & DC-DC Passives
- (near U7) JTAG Programming Interface
- Test and Reset Buttons
- User LEDs
- (near C31) U5, Pin 27
- (near C32) U5, Pin 11
- U5, Pin 19
- (near C38) U5, Pin 28
- U5, Pin 32
- (near L4) Place L4 and C37 close to U5, Pin 18

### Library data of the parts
C19 = GRM155R71C103KA01D: CAP, CERM, 0.01 µF, 16 V, +/- 10%, X7R, 0402; Manufacturer: MuRata; Polarized: N; CompType: Capacitor; Value: 0.01uF; U/M: EA; Cap_F: 0.00000001; Tolerance_%: 10; Value1: Unknown; VDC_V: 16; Value2: 16V; TaMin_C: -55; TaMax_C: 125; AEC Category: Q200
C20 C22 C28 C29 = GRM1555C1E120JA01D: CAP, CERM, 12 pF, 25 V, +/- 5%, C0G/NP0, 0402; Manufacturer: MuRata; Polarized: N; CompType: Capacitor; Value: 12pF; U/M: EA; Cap_F: 0.000000000012; Tolerance_%: 5; Value1: Unknown; VDC_V: 25; Value2: 25V; TaMin_C: -55; TaMax_C: 125; AEC Category: Q200
C21 = GRM1555C1H120JA01D: CAP, CERM, 12 pF, 50 V, +/- 5%, C0G/NP0, 0402; Manufacturer: MuRata; Polarized: N; CompType: Capacitor; Value: 12pF; U/M: EA; Cap_F: 0.000000000012; Tolerance_%: 5; Value1: Unknown; VDC_V: 50; Value2: 50V; TaMin_C: -55; TaMax_C: 125; Cap_Case: 0402; AEC Category: Q200
C23 C24 = GRM1555C1H1R2BA01D: CAP, CERM, 1.2 pF, 50 V, +/- 8.3%, C0G/NP0, 0402; Manufacturer: MuRata; Polarized: N; CompType: Capacitor; Value: 1.2pF; U/M: EA; Cap_F: 0.0000000000012; Tolerance_%: 8.3; Value1: Unknown; VDC_V: 50; Value2: 50V; TaMin_C: -55; TaMax_C: 125; Cap_Case: 0402; AEC Category: Q200
C25 C26 C30 C40 = Capacitor: CAP, CERM, xxxF, xxV, [TempCo], xx%, [PackageReference]; Polarized: N; U/M: EA
C27 = GRM155R61A105KE15D: CAP, CERM, 1 µF, 10 V, +/- 10%, X5R, 0402; Manufacturer: MuRata; Polarized: N; CompType: Capacitor; Value: 1uF; U/M: EA; Cap_F: 0.000001; Tolerance_%: 10; Value1: Unknown; Value2: 10V; TaMin_C: -55; TaMax_C: 85; AEC Category: Q200
C31 C38 C39 = GRM155R70J104KA01D: CAP, CERM, 0.1 µF, 6.3 V, +/- 10%, X7R, 0402; Manufacturer: MuRata; Polarized: N; CompType: Capacitor; Value: 0.1uF; U/M: EA; Cap_F: 0.0000001; Tolerance_%: 10; Value1: Unknown; VDC_V: 6.3; TaMin_C: -55; TaMax_C: 125; Cap_Case: 0402
C32 = GRM155R70J104KA01D: CAP, CERM, 0.1 µF, 6.3 V, +/- 10%, X7R, 0402; Manufacturer: MuRata; Polarized: N; CompType: Capacitor; Value: 0.1uF; U/M: EA; Cap_F: 0.0000001; Tolerance_%: 10; Value1: Unknown; VDC_V: 6.3; TaMin_C: -55; TaMax_C: 125
C33 C37 = GRM188R60J106ME47D: CAP, CERM, 10 µF, 6.3 V, +/- 20%, X5R, 0603; Manufacturer: MuRata; Polarized: N; CompType: Capacitor; Value: 10uF; U/M: EA; Cap_F: 0.00001; Tolerance_%: 20; ESR_ohm: 0.009; Value1: 0.009 ohm; Value2: 6.3V; IRMS_A: 2.74; TaMin_C: -55; TaMax_C: 125; AEC Category: Q200
C34 = GRM188R71E104KA01D: CAP, CERM, 0.1 µF, 25 V, +/- 10%, X7R, 0603; Manufacturer: MuRata; Polarized: N; CompType: Capacitor; Value: 0.1uF; U/M: EA; Cap_F: 0.0000001; Tolerance_%: 10; Value1: Unknown; Value2: 25V; TaMin_C: -55; TaMax_C: 125; AEC Category: Q200
C35 C36 = C1005X7R1H222K: CAP, CERM, 2200 pF, 50 V, +/- 10%, X7R, 0402; Manufacturer: TDK; Polarized: N; CompType: Capacitor; Value: 2200pF; U/M: EA; Cap_F: 0.0000000022; Tolerance_%: 10; ESR_ohm: 0.1433; Value1: 0.1433 ohm; VDC_V: 50; TaMin_C: -55; TaMax_C: 125; AEC Category: Q200
D1 = LS L29K-G1J2-1-Z: LED, Red, SMD; Manufacturer: OSRAM; Vf_V: 1.8; Value2: 1.8V; Io_A: 0.02; Vr_V: 12; Tjmax_C: 110; Value1: W; Angle: 160; U/M: EA
D2 = LY L29K-H1K2-26-Z: LED, Yellow, SMD; Manufacturer: OSRAM; Vf_V: 1.8; Value2: 1.8V; Io_A: 0.02; Vr_V: 12; Tjmax_C: 110; Value1: W; Angle: 160; U/M: EA
E1 = ANTENNA_DN007A: 2.4GHz PCB Antenna.  There is nothing to buy or mount.; SymbolCreator: a0412235
J6 = 5-146280-3: Header, 2.54mm, 3x1, Gold, TH; Manufacturer: TE Connectivity; SymbolCreator: a0799628; Pitch_mm: 2.54; Gender: Male; Shrouded: N; Row_Count: 1
J7 = CONSMA001-SMD-G: Jack, SMA, PCB, Gold, SMT; Manufacturer: Linx Technologies; SymbolCreator: X0208326; U/M: EA
J8 = GRPB052VWVN-RC: Header, 50mil, 5x2, Gold, TH; Manufacturer: Sullins Connector Solutions; SymbolCreator: a0412235; U/M: EA
L1 = LQG15HS15NJ02D: Inductor, Multilayer, Air Core, 15 nH, 0.3 A, 0.32 ohm, SMD; Manufacturer: MuRata; Value: 15nH; Ind_H: 15.0E-9; Imax_A: 0.3; Irms: 0.3A @ C rise; Isat: 0.3A @ % inductance drop; DCR_ohm: 0.32; Value2: 0.3A; AEC Category: Q200
L2 = LQG15HS2N0S02D: Inductor, Multilayer, Air Core, 2 nH, 0.3 A, 0.1 ohm, SMD; Manufacturer: MuRata; Value: 2nH; Ind_H: 2.0E-9; Imax_A: 0.3; Irms: 0.3A @ C rise; Isat: 0.3A @ % inductance drop; DCR_ohm: 0.1; Value1: 0.1 ohm; Value2: 0.3A; AEC Category: Q200
L3 = BLM18HE152SN1D: Ferrite Bead, 1500 ohm @ 100 MHz, 0.5 A, 0603; Manufacturer: MuRata; Imax_A: 0.5; Value1: 0.5 ohm; Value2: 0.5A; ZTyp@100MHz_Ohm: 1500
L4 = CKS2125100M-T: Inductor, Multilayer, Ferrite, 10uH, 0.11A, 0.52 ohm, SMD; Manufacturer: Taiyo Yuden; Ind_H: 10.0E-6; Imax_A: 0.11; DCR_ohm: 0.52
R8 R9 = CRCW04024K75FKED: RES, 4.75 k, 1%, 0.063 W, 0402; Manufacturer: Vishay-Dale; CompType: Resistor; Value: 4.75k; Res_ohm: 4750; Value_Code: 4k75; Tolerance_%: 1; Power_W: 0.063; Value2: 0.063W; VDC_V: 50; TempCo: 100 ppm/C; EIA_Code: E96; U/M: EA; AEC Category: Q200
R10 R12 = CRCW08050000Z0EA: as R7 on sheet TIDA-00756_CO_Sensor
R11 R13-R16 = CRCW04020000Z0ED: RES, 0, 5%, 0.063 W, 0402; Manufacturer: Vishay-Dale; CompType: Resistor; Value: 0; Value_Code: 0000; Tolerance_%: 5; Power_W: 0.063; Value2: 0.063W; VDC_V: 50; TempCo: 200 ppm/C; EIA_Code: E24; U/M: EA; AEC Category: Q200
R17 = ERJ-6ENF5492V: RES, 54.9 k, 1%, 0.125 W, 0805; Manufacturer: Panasonic; CompType: Resistor; Value: 54.9k; Res_ohm: 54900; Value_Code: 54k9; Tolerance_%: 1; Power_W: 0.125; Value2: 0.125W; TempCo: 100 ppm/C; EIA_Code: E96; U/M: EA; AEC Category: Q200
R18 = ERJ-6ENF1963V: RES, 196 k, 1%, 0.125 W, 0805; Manufacturer: Panasonic; CompType: Resistor; Value: 196k; Res_ohm: 196000; Tolerance_%: 1; Power_W: 0.125; Value2: 0.125W; TempCo: 100 ppm/C; EIA_Code: E96; U/M: EA; AEC Category: Q200
R19 = CRCW040210K0FKED: RES, 10.0 k, 1%, 0.063 W, 0402; Manufacturer: Vishay-Dale; CompType: Resistor; Value: 10.0k; Res_ohm: 10000; Value_Code: 10k0; Tolerance_%: 1; Power_W: 0.063; Value2: 0.063W; VDC_V: 50; TempCo: 100 ppm/C; EIA_Code: E96; U/M: EA; AEC Category: Q200
R20 R21 = CRCW040247K5FKED: RES, 47.5 k, 1%, 0.063 W, 0402; Manufacturer: Vishay-Dale; CompType: Resistor; Res_ohm: 47500; Value: 47.5k; Value_Code: 47k5; Tolerance_%: 1; Power_W: 0.063; Value2: 0.063W; VDC_V: 50; TempCo: 100 ppm/C; EIA_Code: E96; U/M: EA; AEC Category: Q200
R22 = CRCW0805442RFKEA: RES, 442, 1%, 0.125 W, 0805; Manufacturer: Vishay-Dale; CompType: Resistor; Value: 442; Value_Code: 442R; Tolerance_%: 1; Power_W: 0.125; VDC_V: 150; TempCo: 100 ppm/C; EIA_Code: E96; U/M: EA; AEC Category: Q200
R23 = CRCW0805487RFKEA: RES, 487, 1%, 0.125 W, 0805; Manufacturer: Vishay-Dale; CompType: Resistor; Value: 487; Value_Code: 487R; Tolerance_%: 1; Power_W: 0.125; VDC_V: 150; TempCo: 100 ppm/C; EIA_Code: E96; U/M: EA; AEC Category: Q200
S1 S2 = B3U-1000P: SWITCH TACTILE SPST-NO 0.05A 12V; Manufacturer: Omron Electronic Components; SymbolCreator: a0412235; VDC_V: 12; SwitchFunction: Off-Mom; PositionCount: 1; CurrentRating_mA: 50
TP6 = 5004: as TP1 on sheet TIDA-00756_CO_Sensor
TP7 TP8 = 5015: Test Point, Miniature, SMT; Manufacturer: Keystone; CompType: Test Point Loop; U/M: EA
U4 = TMP103AYFFR: Low-Power, Digital Temperature Sensor with Two-Wire Interface in WCSP, YFF0004AAAA; Alternate PartNumber: TMP103AYFFT; Manufacturer: Texas Instruments; SymbolCreator: a0411947; CompType: IC; U/M: EA
U5 = CC2650F128RSMR: Ultra low-power ARM Cortex M3 2.4 GHz Radio MCU, RSM0032B; Alternate PartNumber: CC2650F128RSMT; Manufacturer: Texas Instruments; SymbolCreator: Altium; CompType: IC; U/M: EA
U6 = TPL5111DDCR: Nano-power System Timer for Power Gating, DDC0006A; Alternate PartNumber: TPL5111DDCT; Manufacturer: Texas Instruments; SymbolCreator: a0411947; CompType: IC; U/M: EA
U7-U10 = TPD1E10B06DPYR: ESD in 0402 Package with 10 pF Capacitance and 6 V Breakdown, 1 Channel, -40 to +125 degC, 2-pin X2SON (DPY), Green (RoHS & no Sb/Br); Manufacturer: Texas Instruments; Alternate PartNumber: Equivalent; Breakdown Voltage(Min)(V): 6; Eco-Plan: TBD; IEC 61000-4-2 Air-Gap(+/- kV): 30; IO Capacitance(Typ)(pF): 10; SubFamily: ESD Solution
Y1 = TSX-3225 24.0000MF20G-AC3: Crystal, 24 MHz, 9 pF, SMD; Manufacturer: Epson; SymbolCreator: a0412235; U/M: EA; TaMin_C: -40; TaMax_C: 85; Frequency Stability: ±20ppm
Y2 = FC-12M 32.7680KA-A3: Crystal, 32.768kHz, 12.5pF, SMD; Manufacturer: Epson; SymbolCreator: a0412235; U/M: EA; TaMin_C: -40; TaMax_C: 85; Frequency Stability: ±20ppm

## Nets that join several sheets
GND: TIDA-00756_CO_Sensor (26 pins), TIDA-00756_Hardware (H1.1 H2.1 H3.1 H4.1), TIDA-00756_MCU (52 pins)
V_BATT: TIDA-00756_CO_Sensor (16 pins), TIDA-00756_MCU (L3.1 R16.2 U6.1)
CO_OUT: TIDA-00756_CO_Sensor (5 pins), TIDA-00756_MCU (U5.23)
COMP_OUT: TIDA-00756_CO_Sensor (TP2.1 U3.4), TIDA-00756_MCU (U5.22)
SENSOR_TEST: TIDA-00756_CO_Sensor (Q2.3 R5.2), TIDA-00756_MCU (U5.16)

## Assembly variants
001: not fitted C1 C2 C3 C5 C6 C7 C11 C20 C22 C23 C25 C26 C30 C40 J3 J4 J5 J7 R13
